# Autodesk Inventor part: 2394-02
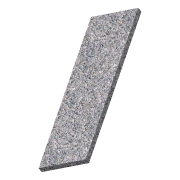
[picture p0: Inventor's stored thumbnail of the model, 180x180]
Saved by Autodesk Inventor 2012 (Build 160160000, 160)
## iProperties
Created: 2011-02
Part Number: 2394-02
Material: Default
Document SubType Name: Modeling
Designer: Beta-8540w
Density: 1 g/cm^3
bottom_thickness: 0.130 in
Author: Beta-8540w
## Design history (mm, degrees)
derived "c15-11.ipt" dims "d2" = 15.875, "d3" = 0, "d4" = 4.4958, "d12" = 4.4958, "d22" = 6.35, "d23" = 0, "d24" = 9.652, "d26" = 6.35, "d27" = 0, "d72" = 19.05, "d73" = 19.05, "d74" = 3.302, "d75" = 3.302, "d76" = 12.7, "drawer_width" = 508, "drawer_height" = 152.4, "dbl_pull_width" = 101.6, "back_width" = 469.9, "bottom_thickness" = 3.302
body "Solid1"
feature "Solid1::c15-11.ipt" dims "d2" = 15.875, "d3" = 0, "d4" = 4.4958, "d12" = 4.4958, "d22" = 6.35, "d23" = 0, "d24" = 9.652, "d26" = 6.35, "d27" = 0, "d72" = 19.05, "d73" = 19.05, "d74" = 3.302, "d75" = 3.302, "d76" = 12.7, "drawer_width" = 508, "drawer_height" = 152.4, "dbl_pull_width" = 101.6, "back_width" = 469.9, "bottom_thickness" = 3.302, "ScaleForDerivedMember" = 10
tag "TaggingFeature1"
